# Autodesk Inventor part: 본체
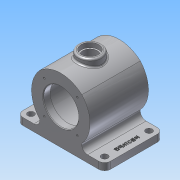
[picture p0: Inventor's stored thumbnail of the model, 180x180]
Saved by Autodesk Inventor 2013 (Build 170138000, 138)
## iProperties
Company: 한국ATC센터
Created: 2014-08
Part Number: 본체
Document SubType Name: Modeling
Designer: KYOUNG IL JANG
Density: 2.71 g/cm^3
Material: 알루미늄 6061
Mass: 1595.16 g
Surface Area: 933.369 cm^2
Volume: 588.618 cm^3
Author: KYOUNG IL JANG
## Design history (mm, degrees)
sketch "스케치1"
  geometry: L1 (-50, 0)-(50, 0); L2 (-36.062, 36.062)-(36.062, 36.062); L3 (36.062, 36.062)-(36.062, -36.062); L4 (36.062, -36.062)-(-36.062, -36.062); L5 (-36.062, -36.062)-(-36.062, 36.062); A1 r 53.623 centre (-3.623, 0) between (36.062, -36.062) and (36.062, 36.062); A2 r 53.623 centre (3.623, 0) between (-36.062, 36.062) and (-36.062, -36.062); A3 r 53.623 centre (0, -3.623) between (36.062, 36.062) and (-36.062, 36.062); A4 r 53.623 centre (0, 3.623) between (-36.062, -36.062) and (36.062, -36.062); 4 further points
  constraints: 11 point on circle, 10 end point, 5 coincident, 4 centre point, 4 horizontal alignment, 3 equal radius, 2 horizontal, 2 parallel, 2 perpendicular, 1 midpoint
  dimensions: "d83" = 51 distance of L2.end point (0, 0); "d84" = 100 distance of L1.end L1.start
extrude "돌출1" new body sketch "스케치1" stored distance "d9" = 100; taper "d10" = 0 deg
node "작업 평면1"
sketch "스케치2"
  geometry: L1 (75, 50)-(-75, 50); L2 (-75, 50)-(-75, -50); L3 (-75, -50)-(75, -50); L4 (75, -50)-(75, 50); 4 further points
  constraints: 8 end point, 3 midpoint, 2 parallel, 2 vertical alignment, 1 horizontal, 1 horizontal alignment, 1 perpendicular
  dimensions: "d14" = 150 distance of L2.end L3.end; "d82" = 100 distance of L1.end L2.end
extrude "돌출2" join sketch "스케치2" distance "d15" = 12; taper "d16" = 0 deg
node "작업 평면3"
  node "작업 평면4"
sketch "스케치3"
  geometry: C1 r 20 at (0, 0); 1 further point
  constraints: 2 coincident, 1 centre point
  dimensions: "d19" = 40 diameter of C1
extrude "돌출3" join sketch "스케치3" stored distance "d23" = 12; taper "d24" = 0 deg
node "작업 평면6"
  node "작업 평면5"
sketch "스케치4"
  geometry: C1 r 37.5 at (0, 0); 1 further point
  constraints: 1 centre point, 1 coincident
  dimensions: "d25" = 75 diameter of C1
extrude "돌출4" cut sketch "스케치4" stored distance "d26" = 76; taper "d27" = 0 deg
sketch "스케치5"
  geometry: C1 r 30 at (0, 0); 1 further point
  constraints: 1 centre point, 1 coincident
  dimensions: "d28" = 60 diameter of C1
extrude "돌출5" cut sketch "스케치5" stored distance "d29" = 116; taper "d30" = 0 deg
hole "구멍1" diameter "d33" = 25; stored, may be unused: countersink angle "d37" = 90 deg, drill point angle "d39" = 0 deg; dims "d31" = 10, "d32" = 10, "d34" = 6, "d35" = 30, "d36" = 8, "d38" = 40
sketch "스케치6"
  geometry: L1 (-75, -50)-(-75, 50) reference; L2 (-75, 50)-(75, 50) reference; L3 (75, -50)-(-75, -50) reference; L4 (75, 50)-(75, -50) reference; L5 (0, -50)-(0, 50); L6 (-75, 0)-(75, 0); L7 (-63, -38)-(63, 38); C1 r 5.5 at (-63, -38); C2 r 5.5 at (-63, 38); C3 r 5.5 at (63, -38); C4 r 5.5 at (63, 38); 2 further points
  constraints: 6 end point, 6 midpoint, 4 centre point, 2 equal radius, 2 horizontal alignment, 2 vertical alignment
  dimensions: "d49" = 11 diameter of C1; "d50" = 11 diameter of C2; "d100" = 12 distance from line of L2 C2.centre; "d101" = 12 distance from line of C2.centre L1
extrude "돌출6" cut sketch "스케치6" distance "d53" = 116; taper "d54" = 0 deg
sketch "스케치8"
  geometry: L1 (75, 50)-(75, -50) reference; 2 further points
  constraints: 1 horizontal alignment, 1 other
  dimensions: "d55" = 12 distance from line of L1 point (63, 0)
feature "엠보싱1" sketch "스케치8" dims "d57" = 1, "d58" = 0, "d83" = 51, "d84" = 100
fillet "모깎기2" dims "d60" = 10
fillet "모깎기5" dims "d63" = 10
fillet "모깎기7" dims "d65" = 3
sketch "스케치9"
  geometry: L1 (0, 0)-(-28.284, 28.284); L2 (0, 0)-(0, 40); C1 r 30 at (0, 0) reference; A1 r 40 centre (0, 0) between (-28.284, 28.284) and (0, 40); 1 further point
  constraints: 4 end point, 2 coincident, 2 point on circle, 1 centre point, 1 vertical
  dimensions: "d66" = 80 diameter of A1; "d67" = 45 deg angle of L1 L2
hole "M4" sketch "스케치9" at (-28.284, 28.284) diameter "d68" = 3.242; stored, may be unused: countersink angle "d72" = 90 deg, drill point angle "d74" = 118 deg; dims "d69" = 8, "d70" = 30, "d71" = 8, "d73" = 10
fillet "모깎기8" dims "d78" = 3
chamfer "모따기1" distance "d79" = 1; stored, may be unused: second distance "d80" = 2, angle "d81" = 45 deg
node "솔리드1"
pattern_circular "원형 패턴1" dims angle "d76" = 360 deg
mirror "대칭1"
